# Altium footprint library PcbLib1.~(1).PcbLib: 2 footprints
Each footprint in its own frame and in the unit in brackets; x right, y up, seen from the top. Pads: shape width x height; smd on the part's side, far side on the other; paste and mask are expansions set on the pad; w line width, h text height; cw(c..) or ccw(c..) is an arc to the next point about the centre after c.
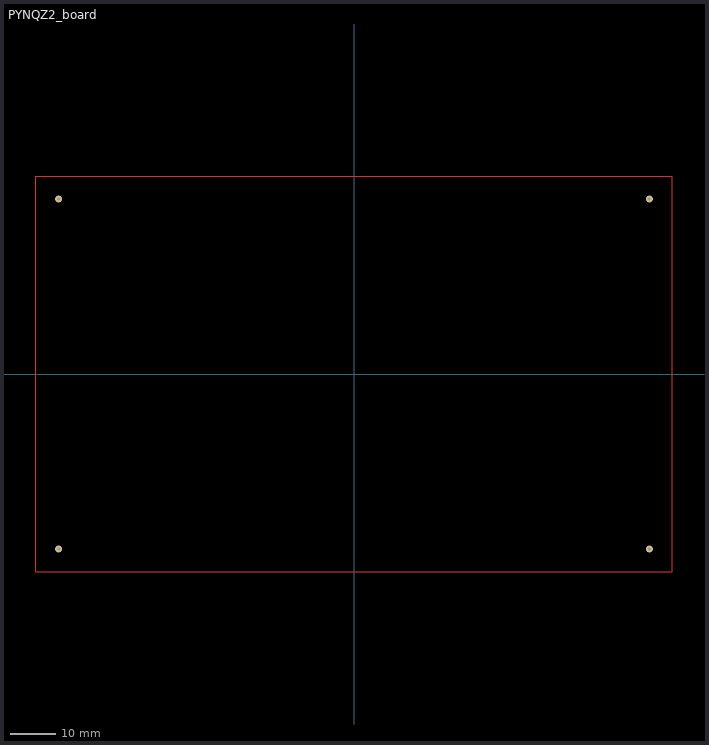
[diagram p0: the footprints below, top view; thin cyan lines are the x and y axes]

## PCBComponent_1 [mm]

## PYNQZ2_board [mil]
pads (4):
  round 60 hole 30: 0(-2559.06,-1515.75) 0(-2559.06,1515.75) 0(2559.06,-1515.75) 0(2559.06,1515.75)
Top Layer:
  lines w10: -2755.91,-1712.6 2755.91,-1712.6 2755.91,1712.6 -2755.91,1712.6 -2755.91,-1712.6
